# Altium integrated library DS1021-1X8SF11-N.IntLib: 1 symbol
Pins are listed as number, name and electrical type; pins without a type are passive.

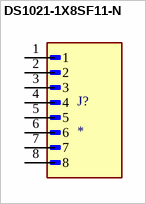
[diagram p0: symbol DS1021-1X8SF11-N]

## DS1021-1X8SF11-N
designator J?
8 position 2.54mm single row vertical pin header through hole; MF: Connfly; MP: DS1021-1X8SF11-N
footprint CONNFLY_DS1021-1X8SF11-N
pins: 1, 2, 3, 4, 5, 6, 7, 8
